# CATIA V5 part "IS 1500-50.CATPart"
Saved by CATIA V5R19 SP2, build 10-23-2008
Part number: IS 1500-50
Bounding box of the stored display mesh (mm): x -37.351 to 37.351, y -37.351 to 37.351, z 0 to 210
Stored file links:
  C:\Users\Bora\Desktop\3D Katı model\IS serisi\IS 1500\IS 1500-50.CATPart
  C:\Program Files\Dassault Systemes\B19\intel_a\reffiles\standard\MetricThickPitch.txt
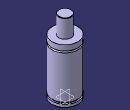
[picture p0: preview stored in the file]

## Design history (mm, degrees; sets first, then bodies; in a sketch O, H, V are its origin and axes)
Body1 (main body)
  Sketch1 on yz-plane, origin (0, 0, 0), H (0, 1, 0), V (0, 0, 1)
    point P1 (37.5, 141.5)
    point P2 (37.5, 136.5)
    point P5 (18, 209)
    point P7 (18, 209)
    point P12 (37.5, 136.5)
    point P13 (37.5, 141.5)
    arc A1 centre (37.5, 139) radius 2.5 from (37.5, 141.5) to (37.5, 136.5) ccw
    line L1 (37.5, 0) -> (37.5, 8)
    line L2 (18, 209) -> (18, 157)
    arc A2 centre (17, 209) radius 1 from (18, 209) to (17, 210) ccw
    line L3 (33.5, 13) -> (33.5, 8)
    line L4 (37.5, 13) -> (37.5, 136.5)
    line L5 (37.5, 141.5) -> (37.5, 157)
    line L6 (17, 210) -> (0, 210)
    point P15 (0, 210)
    line L7 (18, 157) -> (37.5, 157)
    line L8 (0, 0) -> (37.5, 0)
    line L9 (33.5, 8) -> (37.5, 8)
    line L10 (33.5, 13) -> (37.5, 13)
    coincidence: P15 V, P1 P13, P2 P12, P5 P7
    tangency: L6 A2
    horizontal: L7 H, L8 H, L9 H, L10 H
  Shaft1: profile Sketch1, axis Sketch1.V, angle 360
  Sketch2 on face of Shaft1 from Sketch1.L8, origin (0, 0, 0), H (1, 0, 0), V (0, -1, 0)
    point P1 (20, 0)
    distance P1 V = 20
  Hole1: placed by Sketch2, at (20, 0, 0) direction (0, 0, 1), diameter 6.647, depth 13, threaded "M8", thread diameter 8, thread depth 13, pitch 1.25
  CircPattern1: of Hole1, instances 4, angular step 90, axis from xy-plane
